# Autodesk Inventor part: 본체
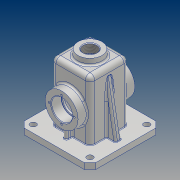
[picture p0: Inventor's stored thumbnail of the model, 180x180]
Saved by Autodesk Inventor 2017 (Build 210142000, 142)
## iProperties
Part Number: 본체
Material: 알루미늄 6061
Document SubType Name: Modeling
Designer: 20
Density: 2.7 g/cm^3
Appearance: 알루미늄 - 평지
Mass: 791.702 g
Surface Area: 897.811 cm^2
Volume: 293.223 cm^3
Author: 20
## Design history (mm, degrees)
sketch "스케치1"
  geometry: L1 (-32.5, 32.5)-(32.5, 32.5); L2 (32.5, 32.5)-(32.5, -32.5); L3 (32.5, -32.5)-(-32.5, -32.5); L4 (-32.5, -32.5)-(-32.5, 32.5); L5 (-32.5, 32.5)-(32.5, -32.5); L6 (32.5, 32.5)-(-32.5, -32.5); 1 further point
  constraints: 12 end point, 2 midpoint, 2 parallel, 1 horizontal, 1 perpendicular
  dimensions: "d0" = 65 distance of L2.end L3.end; "d1" = 65 distance of L1.end L2.end
extrude "돌출1" new body sketch "스케치1" distance "d2" = 110; taper "d3" = 0 deg
sketch "스케치2"
  geometry: L1 (-27.5, -27.5)-(27.5, -27.5); L2 (27.5, -27.5)-(27.5, 27.5); L3 (27.5, 27.5)-(-27.5, 27.5); L4 (-27.5, 27.5)-(-27.5, -27.5); L5 (-27.5, -27.5)-(27.5, 27.5); L6 (27.5, -27.5)-(-27.5, 27.5); 1 further point
  constraints: 12 end point, 2 midpoint, 2 parallel, 1 horizontal, 1 perpendicular
  dimensions: "d4" = 55 distance of L3.end L2.end; "d5" = 55 distance of L2.end L1.end
extrude "돌출2" cut sketch "스케치2" distance "d6" = 105; taper "d7" = 0 deg
sketch "스케치3"
  geometry: L1 (-60, -60)-(60, -60); L2 (60, -60)-(60, 60); L3 (60, 60)-(-60, 60); L4 (-60, 60)-(-60, -60); L5 (-60, -60)-(60, 60); L6 (60, -60)-(-60, 60); L7 (-32.5, 32.5)-(-32.5, -32.5) reference; L8 (-32.5, -32.5)-(32.5, -32.5) reference; L9 (32.5, -32.5)-(32.5, 32.5) reference; L10 (32.5, 32.5)-(-32.5, 32.5) reference; 1 further point
  constraints: 12 end point, 2 midpoint, 2 parallel, 1 horizontal, 1 perpendicular
  dimensions: "d8" = 120 distance of L3.end L2.end; "d9" = 120 distance of L2.end L1.end
extrude "돌출3" join sketch "스케치3" distance "d10" = 10; taper "d11" = 0 deg
sketch "스케치4"
  geometry: C1 r 20 at (0, 0); 1 further point
  constraints: 1 centre point, 1 coincident
  dimensions: "d12" = 40 diameter of C1
extrude "돌출4" join sketch "스케치4" distance "d13" = 10; taper "d14" = 0 deg
feature "면 기울기2" dims angle "d105" = 5 deg
sketch "스케치5"
  geometry: L1 (92.5, -110)-(-27.5, -110) reference; C1 r 27.5 at (32.5, -55); 2 further points
  constraints: 1 centre point, 1 midpoint, 1 vertical alignment
  dimensions: "d16" = 55 diameter of C1; "d17" = 55 distance from line of L1 C1.centre
extrude "돌출5" join sketch "스케치5" distance "d18" = 15; taper "d19" = 0 deg
sketch "스케치6"
  geometry: C1 r 27.5 at (0, 0) reference; C2 r 17.5 at (0, 0); 1 further point
  constraints: 1 centre point, 1 coincident
  dimensions: "d20" = 35 diameter of C2
extrude "돌출6" cut sketch "스케치6" distance "d21" = 17; taper "d22" = 0 deg
sketch "스케치7"
  geometry: C1 r 17.5 at (0, 0) reference; C2 r 15 at (0, 0); 1 further point
  constraints: 1 centre point, 1 coincident
  dimensions: "d23" = 30 diameter of C2
extrude "돌출7" cut sketch "스케치7" distance "d24" = 3; taper "d25" = 0 deg
sketch "스케치8" dims "d26" = 42
  geometry: L1 (60, -55)-(-60, -55) reference; C1 r 15 at (0, 0) reference; 4 further points
  constraints: 2 vertical alignment, 1 coincident, 1 midpoint, 2 other
hole "구멍1" sketch "스케치8" at (0, 21) diameter "d27" = 3.242; stored, may be unused: countersink angle "d31" = 90 deg, drill point angle "d33" = 118 deg; dims "d28" = 8, "d29" = 4, "d30" = 2, "d32" = 10
sketch "스케치9"
  geometry: L1 (-42.5, 9.836)-(-42.5, 24.836); L2 (60, 10)-(-60, 10) reference; L3 (-27.5, 0)-(-27.5, 105) reference; 1 further point
  constraints: 2 end point, 1 vertical
  dimensions: "d37" = 15 distance between parallel lines of L1 L3; "d38" = 15 distance of L1.start L1.end
feature "리브1" sketch "스케치9" dims "d39" = 1, "d40" = 6, "d41" = 0, "d42" = 0, "d43" = 1, "d44" = 1
sketch "스케치11"
  geometry: L1 (60, 10)-(-60, 10) reference; L2 (42.5, 10)-(42.5, 25); L3 (27.5, 0)-(27.5, 105) reference; 1 further point
  constraints: 2 end point, 1 point on line, 1 vertical
  dimensions: "d45" = 15 distance between parallel lines of L3 L2; "d46" = 15 distance of L2.start L2.end
feature "리브2" sketch "스케치11" dims "d47" = 1, "d48" = 6, "d49" = 0, "d50" = 0, "d51" = 1, "d52" = 1
sketch "스케치12"
  geometry: L1 (-60, 10)-(60, 10) reference; L2 (-48, 10)-(-37.581, 69.088); L3 (-60, 0)-(-60, 10) reference; 1 further point
  constraints: 2 end point, 1 point on line
  dimensions: "d53" = 12 distance from line of L2.start L3; "d54" = 10 deg angle of L3 L2; "d55" = 60 distance of L2.start L2.end
feature "리브3" sketch "스케치12" dims "d56" = 1, "d57" = 10, "d58" = 0, "d59" = 0, "d60" = 1, "d61" = 1
hole "구멍2" diameter "d64" = 22.835; stored, may be unused: countersink angle "d68" = 90 deg, drill point angle "d70" = 118 deg; dims "d62" = 10, "d63" = 10, "d65" = 50, "d66" = 4, "d67" = 2, "d69" = 30
sketch "스케치13"
  geometry: L1 (-60, 60)-(-60, -60) reference; L2 (60, 60)-(-60, 60) reference; C1 r 5 at (-47.5, 47.5); 1 further point
  constraints: 1 centre point
  dimensions: "d71" = 10 diameter of C1; "d72" = 12.5 distance from line of C1.centre L1; "d73" = 12.5 distance from line of L2 C1.centre
extrude "돌출8" cut sketch "스케치13" stored distance "d74" = 3; taper "d75" = 0 deg
chamfer "모따기1" distance "d82" = 10; stored, may be unused: second distance "d83" = 2, angle "d84" = 45 deg
chamfer "모따기2" distance "d85" = 1; stored, may be unused: second distance "d86" = 2, angle "d87" = 45 deg
fillet "모깎기1" dims "d88" = 0.3
fillet "모깎기2" dims "d89" = 3
fillet "모깎기3" dims "d90" = 3
fillet "모깎기4" dims "d91" = 8
fillet "모깎기5" dims "d92" = 8
fillet "모깎기7" dims "d94" = 3
fillet "모깎기8" dims "d95" = 3
fillet "모깎기9" dims "d96" = 3
fillet "모깎기10" dims "d97" = 3
fillet "모깎기12" dims "d99" = 1
node "작업 평면1"
sketch "스케치14"
  geometry: L1 (57, 0)-(57, 91) reference; L2 (4.5, -18)-(44.5, -18) reference; 2 further points
  constraints: 1 other
  dimensions: "d101" = 32.5 distance from line of point (24.5, 8) L1; "d102" = 26 distance from line of point (24.5, 8) L2
feature "엠보싱1" sketch "스케치14" dims "d8" = 120, "d9" = 120, "d103" = 0.5, "d104" = 0
fillet "모깎기13" dims "d106" = 3
node "솔리드1"
pattern_circular "원형 패턴1" dims angle "d35" = 360 deg
mirror "미러1"
mirror "미러2"
pattern_linear "직사각형 패턴1" dims "d78" = 95, "d81" = 95
